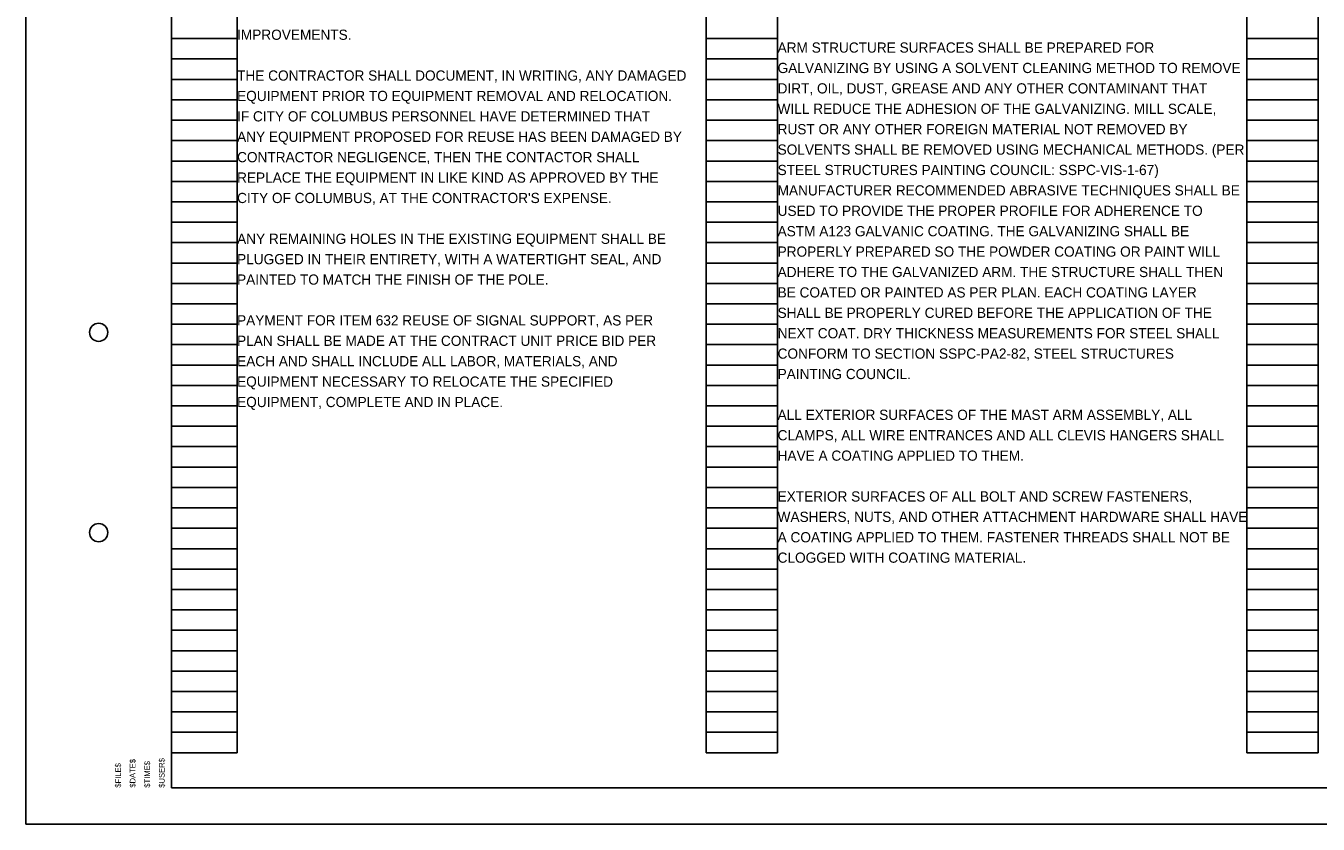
# Model space of a CAD drawing. Extents: x -15.1 to 53.7, y -46.4 to 36.
# Drawn here: x -0.51 to 17.23, y -7.51 to 3.45 of the extents above; entities that cross this region are included whole.
import ezdxf

# ---------------------------------------------------------------- set-up
doc = ezdxf.new("R2010")
doc.units = 0
for name, color, linetype in [('PF_P_Text', 7, 'Continuous'), ('SC_Scratch1', 7, 'Continuous'), ('SH_Cut_Line', 7, 'Continuous'), ('SH_Text', 7, 'Continuous'), ('TX_P_Misc', 7, 'Continuous')]:
    doc.layers.add(name, color=color, linetype=linetype)

msp = doc.modelspace()

# ---------------------------------------------------------------- linework, layer by layer
at = {"layer": 'PF_P_Text'}
msp.add_lwpolyline([(1.494, 13.992), (32.994, 13.992), (32.994, -7.008), (1.494, -7.008)], close=True, dxfattribs=at)
for centre in [(0.494, -0.758), (0.494, -3.508)]:
    msp.add_circle(centre, 0.125, dxfattribs=at)
at = {"layer": 'SC_Scratch1'}
for p, q in [((1.494, -6.528), (1.494, 13.632)), ((2.394, -6.528), (2.394, 13.632)), ((8.834, -6.528), (8.834, 13.632)), ((9.814, -6.528), (9.814, 13.632)), ((16.254, -6.528), (16.254, 13.632)), ((17.234, -6.528), (17.234, 13.632)), ((1.494, 3.272), (2.394, 3.272)), ((8.834, 3.272), (9.814, 3.272)), ((16.254, 3.272), (17.234, 3.272)), ((1.494, 2.992), (2.394, 2.992)), ((8.834, 2.992), (9.814, 2.992)), ((16.254, 2.992), (17.234, 2.992)), ((1.494, 2.712), (2.394, 2.712)), ((8.834, 2.712), (9.814, 2.712)), ((16.254, 2.712), (17.234, 2.712)), ((1.494, 2.432), (2.394, 2.432)), ((8.834, 2.432), (9.814, 2.432)), ((16.254, 2.432), (17.234, 2.432)), ((1.494, 2.152), (2.394, 2.152)), ((8.834, 2.152), (9.814, 2.152)), ((16.254, 2.152), (17.234, 2.152)), ((1.494, 1.872), (2.394, 1.872)), ((8.834, 1.872), (9.814, 1.872)), ((16.254, 1.872), (17.234, 1.872)), ((1.494, 1.592), (2.394, 1.592)), ((8.834, 1.592), (9.814, 1.592)), ((16.254, 1.592), (17.234, 1.592)), ((1.494, 1.312), (2.394, 1.312)), ((8.834, 1.312), (9.814, 1.312)), ((16.254, 1.312), (17.234, 1.312)), ((1.494, 1.032), (2.394, 1.032)), ((8.834, 1.032), (9.814, 1.032)), ((16.254, 1.032), (17.234, 1.032)), ((1.494, 0.752), (2.394, 0.752)), ((8.834, 0.752), (9.814, 0.752)), ((16.254, 0.752), (17.234, 0.752)), ((1.494, 0.472), (2.394, 0.472)), ((8.834, 0.472), (9.814, 0.472)), ((16.254, 0.472), (17.234, 0.472)), ((1.494, 0.192), (2.394, 0.192)), ((8.834, 0.192), (9.814, 0.192)), ((16.254, 0.192), (17.234, 0.192)), ((1.494, -0.088), (2.394, -0.088)), ((8.834, -0.088), (9.814, -0.088)), ((16.254, -0.088), (17.234, -0.088)), ((1.494, -0.368), (2.394, -0.368)), ((8.834, -0.368), (9.814, -0.368)), ((16.254, -0.368), (17.234, -0.368)), ((1.494, -0.648), (2.394, -0.648)), ((8.834, -0.648), (9.814, -0.648)), ((16.254, -0.648), (17.234, -0.648)), ((1.494, -0.928), (2.394, -0.928)), ((8.834, -0.928), (9.814, -0.928)), ((16.254, -0.928), (17.234, -0.928)), ((1.494, -1.208), (2.394, -1.208)), ((8.834, -1.208), (9.814, -1.208)), ((16.254, -1.208), (17.234, -1.208)), ((1.494, -1.488), (2.394, -1.488)), ((8.834, -1.488), (9.814, -1.488)), ((16.254, -1.488), (17.234, -1.488)), ((1.494, -1.768), (2.394, -1.768)), ((8.834, -1.768), (9.814, -1.768)), ((16.254, -1.768), (17.234, -1.768)), ((1.494, -2.048), (2.394, -2.048)), ((8.834, -2.048), (9.814, -2.048)), ((16.254, -2.048), (17.234, -2.048)), ((1.494, -2.328), (2.394, -2.328)), ((8.834, -2.328), (9.814, -2.328)), ((16.254, -2.328), (17.234, -2.328)), ((1.494, -2.608), (2.394, -2.608)), ((8.834, -2.608), (9.814, -2.608)), ((16.254, -2.608), (17.234, -2.608)), ((1.494, -2.888), (2.394, -2.888)), ((8.834, -2.888), (9.814, -2.888)), ((16.254, -2.888), (17.234, -2.888)), ((1.494, -3.168), (2.394, -3.168)), ((8.834, -3.168), (9.814, -3.168)), ((16.254, -3.168), (17.234, -3.168)), ((1.494, -3.448), (2.394, -3.448)), ((8.834, -3.448), (9.814, -3.448)), ((16.254, -3.448), (17.234, -3.448)), ((1.494, -3.728), (2.394, -3.728)), ((8.834, -3.728), (9.814, -3.728)), ((16.254, -3.728), (17.234, -3.728)), ((1.494, -4.008), (2.394, -4.008)), ((8.834, -4.008), (9.814, -4.008)), ((16.254, -4.008), (17.234, -4.008)), ((1.494, -4.288), (2.394, -4.288)), ((8.834, -4.288), (9.814, -4.288)), ((16.254, -4.288), (17.234, -4.288)), ((1.494, -4.568), (2.394, -4.568)), ((8.834, -4.568), (9.814, -4.568)), ((16.254, -4.568), (17.234, -4.568)), ((1.494, -4.848), (2.394, -4.848)), ((8.834, -4.848), (9.814, -4.848)), ((16.254, -4.848), (17.234, -4.848)), ((1.494, -5.128), (2.394, -5.128)), ((8.834, -5.128), (9.814, -5.128)), ((16.254, -5.128), (17.234, -5.128)), ((1.494, -5.408), (2.394, -5.408)), ((8.834, -5.408), (9.814, -5.408)), ((16.254, -5.408), (17.234, -5.408)), ((1.494, -5.688), (2.394, -5.688)), ((8.834, -5.688), (9.814, -5.688)), ((16.254, -5.688), (17.234, -5.688)), ((1.494, -5.968), (2.394, -5.968)), ((8.834, -5.968), (9.814, -5.968)), ((16.254, -5.968), (17.234, -5.968)), ((1.494, -6.248), (2.394, -6.248)), ((8.834, -6.248), (9.814, -6.248)), ((16.254, -6.248), (17.234, -6.248)), ((1.494, -6.528), (2.394, -6.528)), ((8.834, -6.528), (9.814, -6.528)), ((16.254, -6.528), (17.234, -6.528)), ((-0.506, -7.508), (-0.506, -7.508))]:
    msp.add_line(p, q, dxfattribs=at)
at = {"layer": 'SH_Cut_Line'}
msp.add_lwpolyline([(-0.506, -7.508), (33.494, -7.508), (33.494, 14.492), (-0.506, 14.492)], close=True, dxfattribs=at)

# ---------------------------------------------------------------- texts
at = {"layer": 'SH_Text'}
for s, p in [('IMPROVEMENTS. ', (2.394, 3.255)), ('ARM STRUCTURE SURFACES SHALL BE PREPARED FOR ', (9.814, 3.079)), ('GALVANIZING BY USING A SOLVENT CLEANING METHOD TO REMOVE ', (9.814, 2.799)), ('THE CONTRACTOR SHALL DOCUMENT, IN WRITING, ANY DAMAGED ', (2.394, 2.695)), ('DIRT, OIL, DUST, GREASE AND ANY OTHER CONTAMINANT THAT ', (9.814, 2.519)), ('EQUIPMENT PRIOR TO EQUIPMENT REMOVAL AND RELOCATION. ', (2.394, 2.415)), ('WILL REDUCE THE ADHESION OF THE GALVANIZING. MILL SCALE, ', (9.814, 2.239)), ('IF CITY OF COLUMBUS PERSONNEL HAVE DETERMINED THAT ', (2.394, 2.135)), ('ANY EQUIPMENT PROPOSED FOR REUSE HAS BEEN DAMAGED BY ', (2.394, 1.855)), ('RUST OR ANY OTHER FOREIGN MATERIAL NOT REMOVED BY ', (9.814, 1.959)), ('SOLVENTS SHALL BE REMOVED USING MECHANICAL METHODS. (PER ', (9.814, 1.679)), ('CONTRACTOR NEGLIGENCE, THEN THE CONTACTOR SHALL ', (2.394, 1.575)), ('REPLACE THE EQUIPMENT IN LIKE KIND AS APPROVED BY THE ', (2.394, 1.295)), ('STEEL STRUCTURES PAINTING COUNCIL: SSPC-VIS-1-67) ', (9.814, 1.399)), ('MANUFACTURER RECOMMENDED ABRASIVE TECHNIQUES SHALL BE ', (9.814, 1.119)), ("CITY OF COLUMBUS, AT THE CONTRACTOR'S EXPENSE. ", (2.394, 1.015)), ('USED TO PROVIDE THE PROPER PROFILE FOR ADHERENCE TO ', (9.814, 0.839)), ('ANY REMAINING HOLES IN THE EXISTING EQUIPMENT SHALL BE ', (2.394, 0.455)), ('ASTM A123 GALVANIC COATING. THE GALVANIZING SHALL BE ', (9.814, 0.559)), ('PROPERLY PREPARED SO THE POWDER COATING OR PAINT WILL ', (9.814, 0.279)), ('PLUGGED IN THEIR ENTIRETY, WITH A WATERTIGHT SEAL, AND ', (2.394, 0.175)), ('PAINTED TO MATCH THE FINISH OF THE POLE. ', (2.394, -0.105)), ('ADHERE TO THE GALVANIZED ARM. THE STRUCTURE SHALL THEN ', (9.814, -0.001)), ('BE COATED OR PAINTED AS PER PLAN. EACH COATING LAYER ', (9.814, -0.281)), ('PAYMENT FOR ITEM 632 REUSE OF SIGNAL SUPPORT, AS PER ', (2.394, -0.665)), ('SHALL BE PROPERLY CURED BEFORE THE APPLICATION OF THE ', (9.814, -0.561)), ('NEXT COAT. DRY THICKNESS MEASUREMENTS FOR STEEL SHALL ', (9.814, -0.841)), ('PLAN SHALL BE MADE AT THE CONTRACT UNIT PRICE BID PER ', (2.394, -0.945)), ('CONFORM TO SECTION SSPC-PA2-82, STEEL STRUCTURES ', (9.814, -1.121)), ('EACH AND SHALL INCLUDE ALL LABOR, MATERIALS, AND ', (2.394, -1.225)), ('EQUIPMENT NECESSARY TO RELOCATE THE SPECIFIED ', (2.394, -1.505)), ('PAINTING COUNCIL.', (9.814, -1.401)), ('EQUIPMENT, COMPLETE AND IN PLACE. ', (2.394, -1.785)), ('ALL EXTERIOR SURFACES OF THE MAST ARM ASSEMBLY, ALL ', (9.814, -1.961)), ('CLAMPS, ALL WIRE ENTRANCES AND ALL CLEVIS HANGERS SHALL ', (9.814, -2.241)), ('HAVE A COATING APPLIED TO THEM.  ', (9.814, -2.521)), ('EXTERIOR SURFACES OF ALL BOLT AND SCREW FASTENERS, ', (9.814, -3.081)), ('WASHERS, NUTS, AND OTHER ATTACHMENT HARDWARE SHALL HAVE ', (9.814, -3.361)), ('A COATING APPLIED TO THEM. FASTENER THREADS SHALL NOT BE ', (9.814, -3.641)), ('CLOGGED WITH COATING MATERIAL.', (9.814, -3.921))]:
    msp.add_text(s, height=0.14, dxfattribs=at).set_placement(p)
at = {"layer": 'TX_P_Misc'}
for s, p in [('$FILE$', (0.799, -7.008)), ('$DATE$', (0.999, -7.008)), ('$TIME$', (1.199, -7.008)), ('$USER$', (1.399, -7.008))]:
    msp.add_text(s, height=0.078, rotation=90, dxfattribs=at).set_placement(p)

doc.saveas('drawing.dxf')
